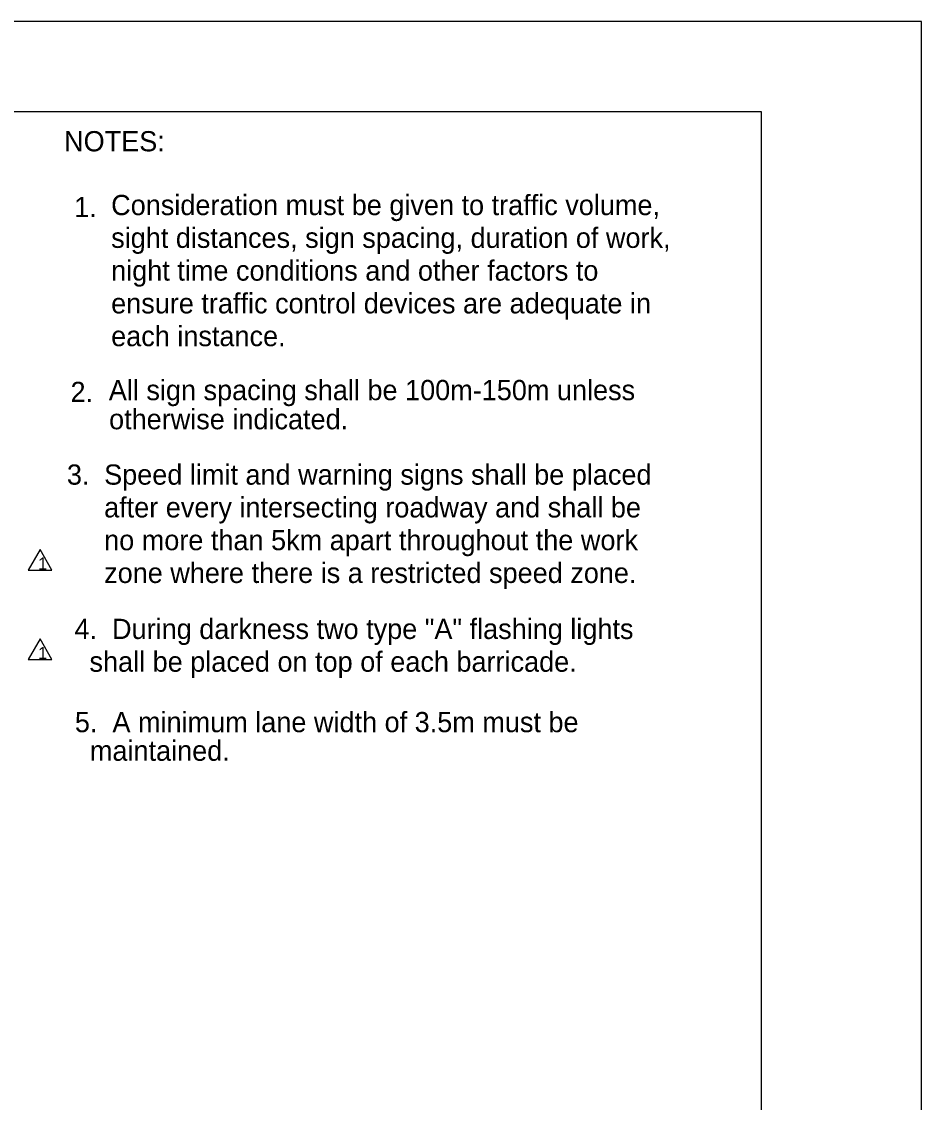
# Model space of a CAD drawing. Extents: x 797 to 1013, y 120 to 399.
# Drawn here: x 905.6 to 1013.2, y 270.1 to 399.4 of the extents above; entities that cross this region are included whole.
import ezdxf

# ---------------------------------------------------------------- set-up
doc = ezdxf.new("R2010")
doc.units = 0
for name, color, linetype in [('Level 1', 7, 'Continuous'), ('Level 10', 7, 'Continuous'), ('Level 60', 7, 'Continuous')]:
    doc.layers.add(name, color=color, linetype=linetype)

msp = doc.modelspace()

# ---------------------------------------------------------------- linework, layer by layer
at = {"layer": 'Level 1'}
for points in [[(907.78, 336.23), (906.37, 333.76), (909.2, 333.76)], [(907.78, 325.53), (906.37, 323.06), (909.2, 323.06)]]:
    msp.add_lwpolyline(points, close=True, dxfattribs=at)
at = {"layer": 'Level 60'}
msp.add_line((1013.16, 399.38), (1013.16, 399.38), dxfattribs=at)
for points in [[(1013.16, 399.38), (797.16, 399.38), (797.16, 120.38), (1013.16, 120.38)], [(994.03, 388.57), (807.16, 388.57), (807.16, 131.19), (994.03, 131.19)]]:
    msp.add_lwpolyline(points, close=True, dxfattribs=at)

# ---------------------------------------------------------------- texts
at = {"layer": 'Level 1'}
for p in [(907.56, 333.82), (907.56, 323.11)]:
    msp.add_text('1', height=1.45, rotation=360, dxfattribs=at).set_placement(p)
at = {"layer": 'Level 10'}
for s, p in [('NOTES:', (910.65, 383.86)), ('1.', (911.85, 375.99)), ('Consideration must be given to traffic volume,', (916.28, 376.23)), ('sight distances, sign spacing, duration of work,', (916.28, 372.31)), ('night time conditions and other factors to', (916.28, 368.39)), ('ensure traffic control devices are adequate in', (916.28, 364.47)), ('each instance.', (916.28, 360.55)), ('2.', (911.42, 353.87)), ('All sign spacing shall be 100m-150m unless', (916, 354.09)), ('otherwise indicated.', (916.03, 350.61)), ('3.', (910.99, 343.98)), ('Speed limit and warning signs shall be placed ', (915.44, 343.98)), ('after every intersecting roadway and shall be ', (915.44, 340.06)), ('no more than 5km apart throughout the work ', (915.44, 336.14)), ('zone where there is a restricted speed zone.', (915.44, 332.22)), ('4.  During darkness two type "A" flashing lights', (911.89, 325.52)), ('  shall be placed on top of each barricade.', (911.89, 321.6)), ('5.  A minimum lane width of 3.5m must be ', (911.94, 314.37)), ('  maintained. ', (911.94, 310.95))]:
    msp.add_text(s, height=2.419, dxfattribs=at).set_placement(p)

doc.saveas('drawing.dxf')
